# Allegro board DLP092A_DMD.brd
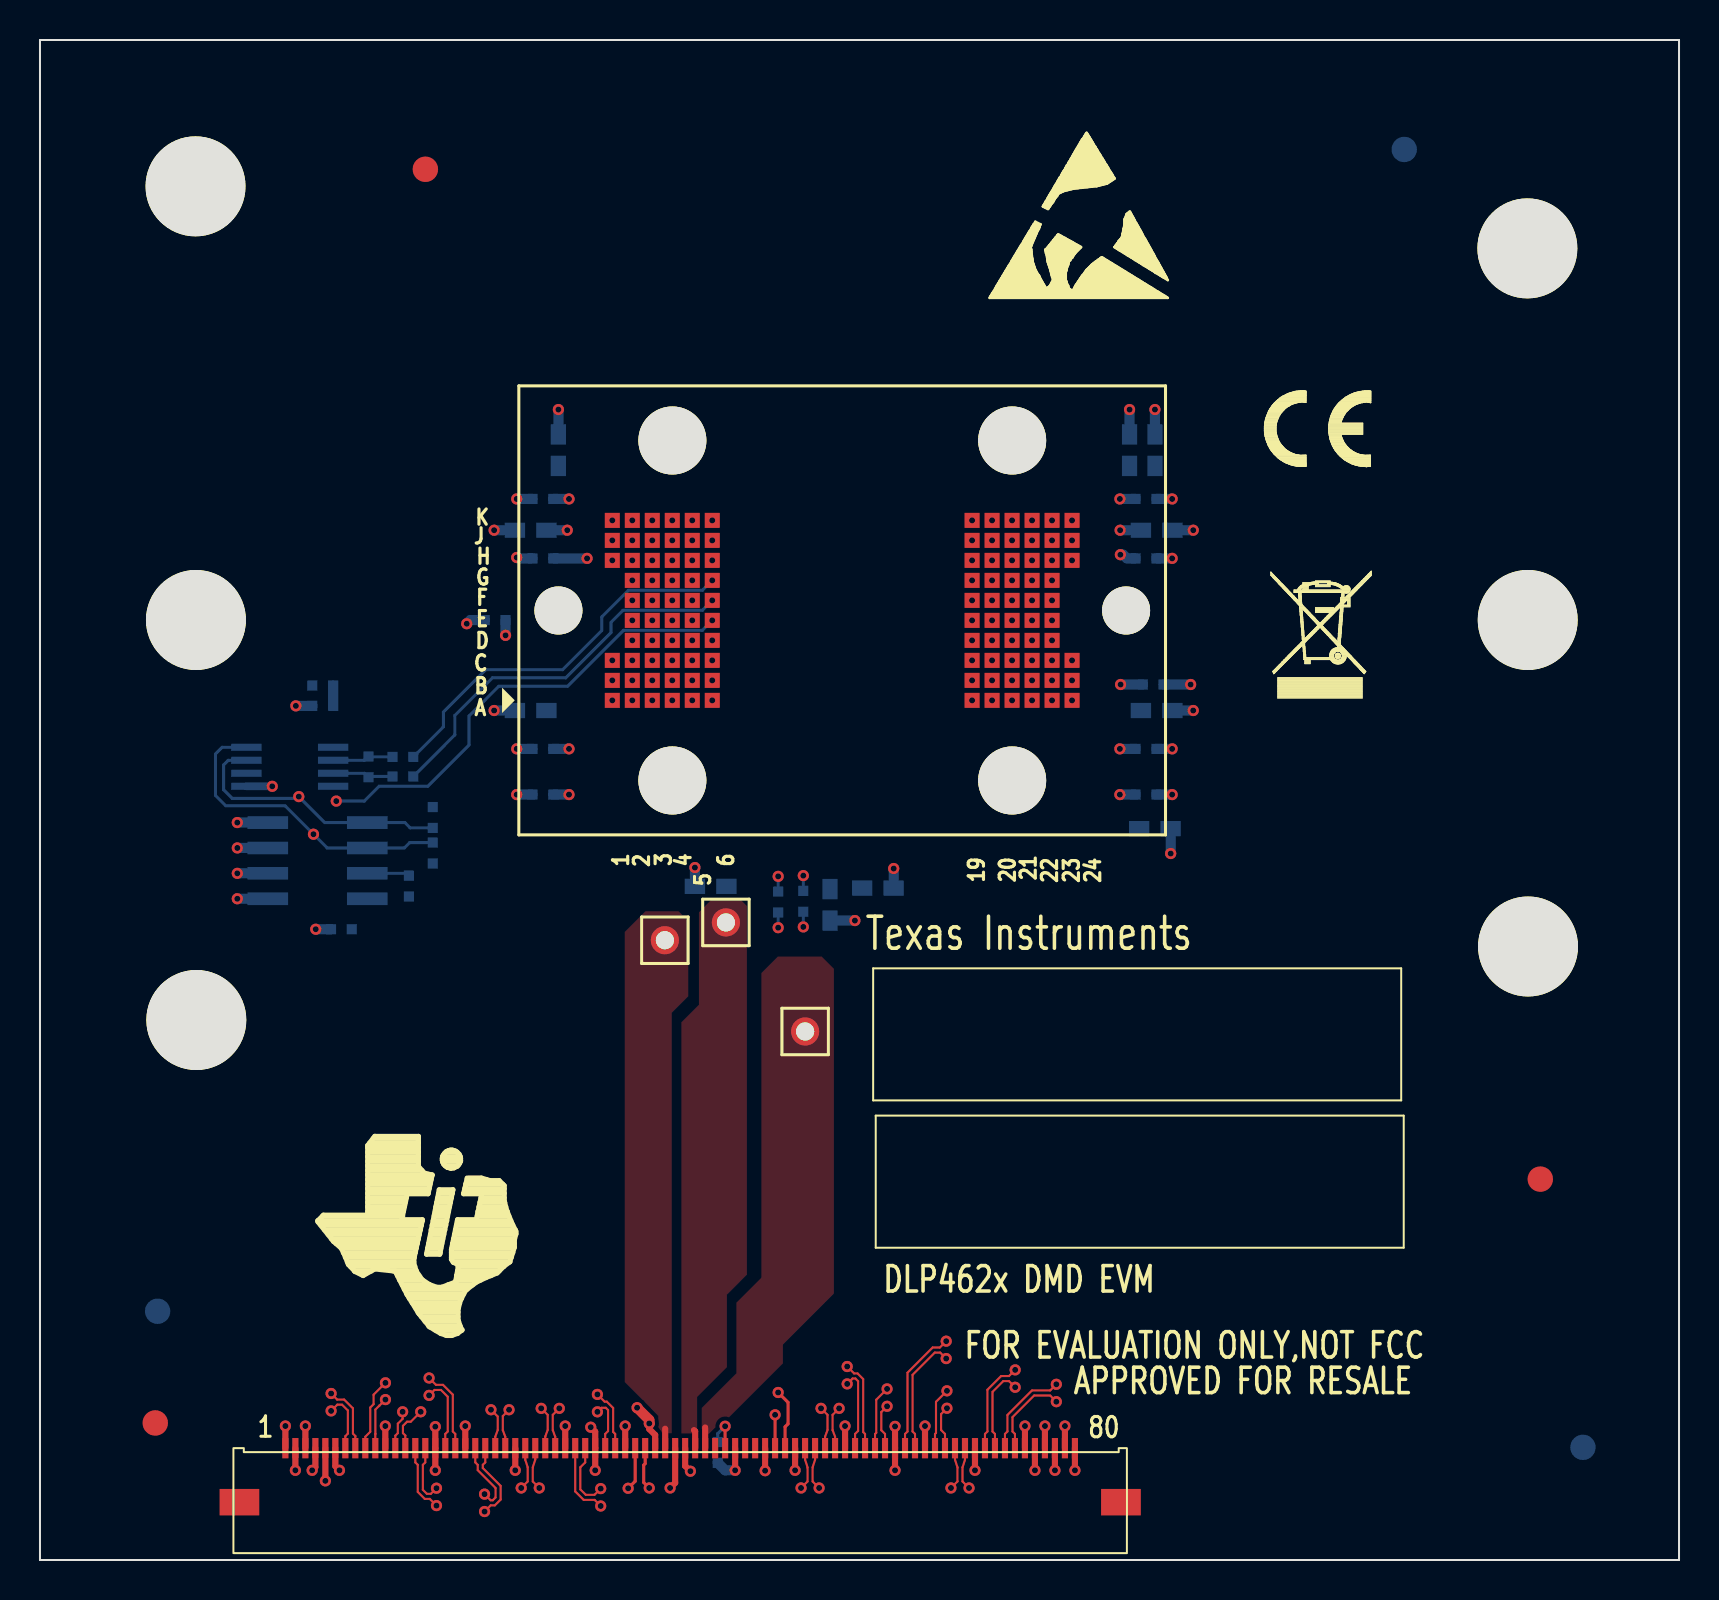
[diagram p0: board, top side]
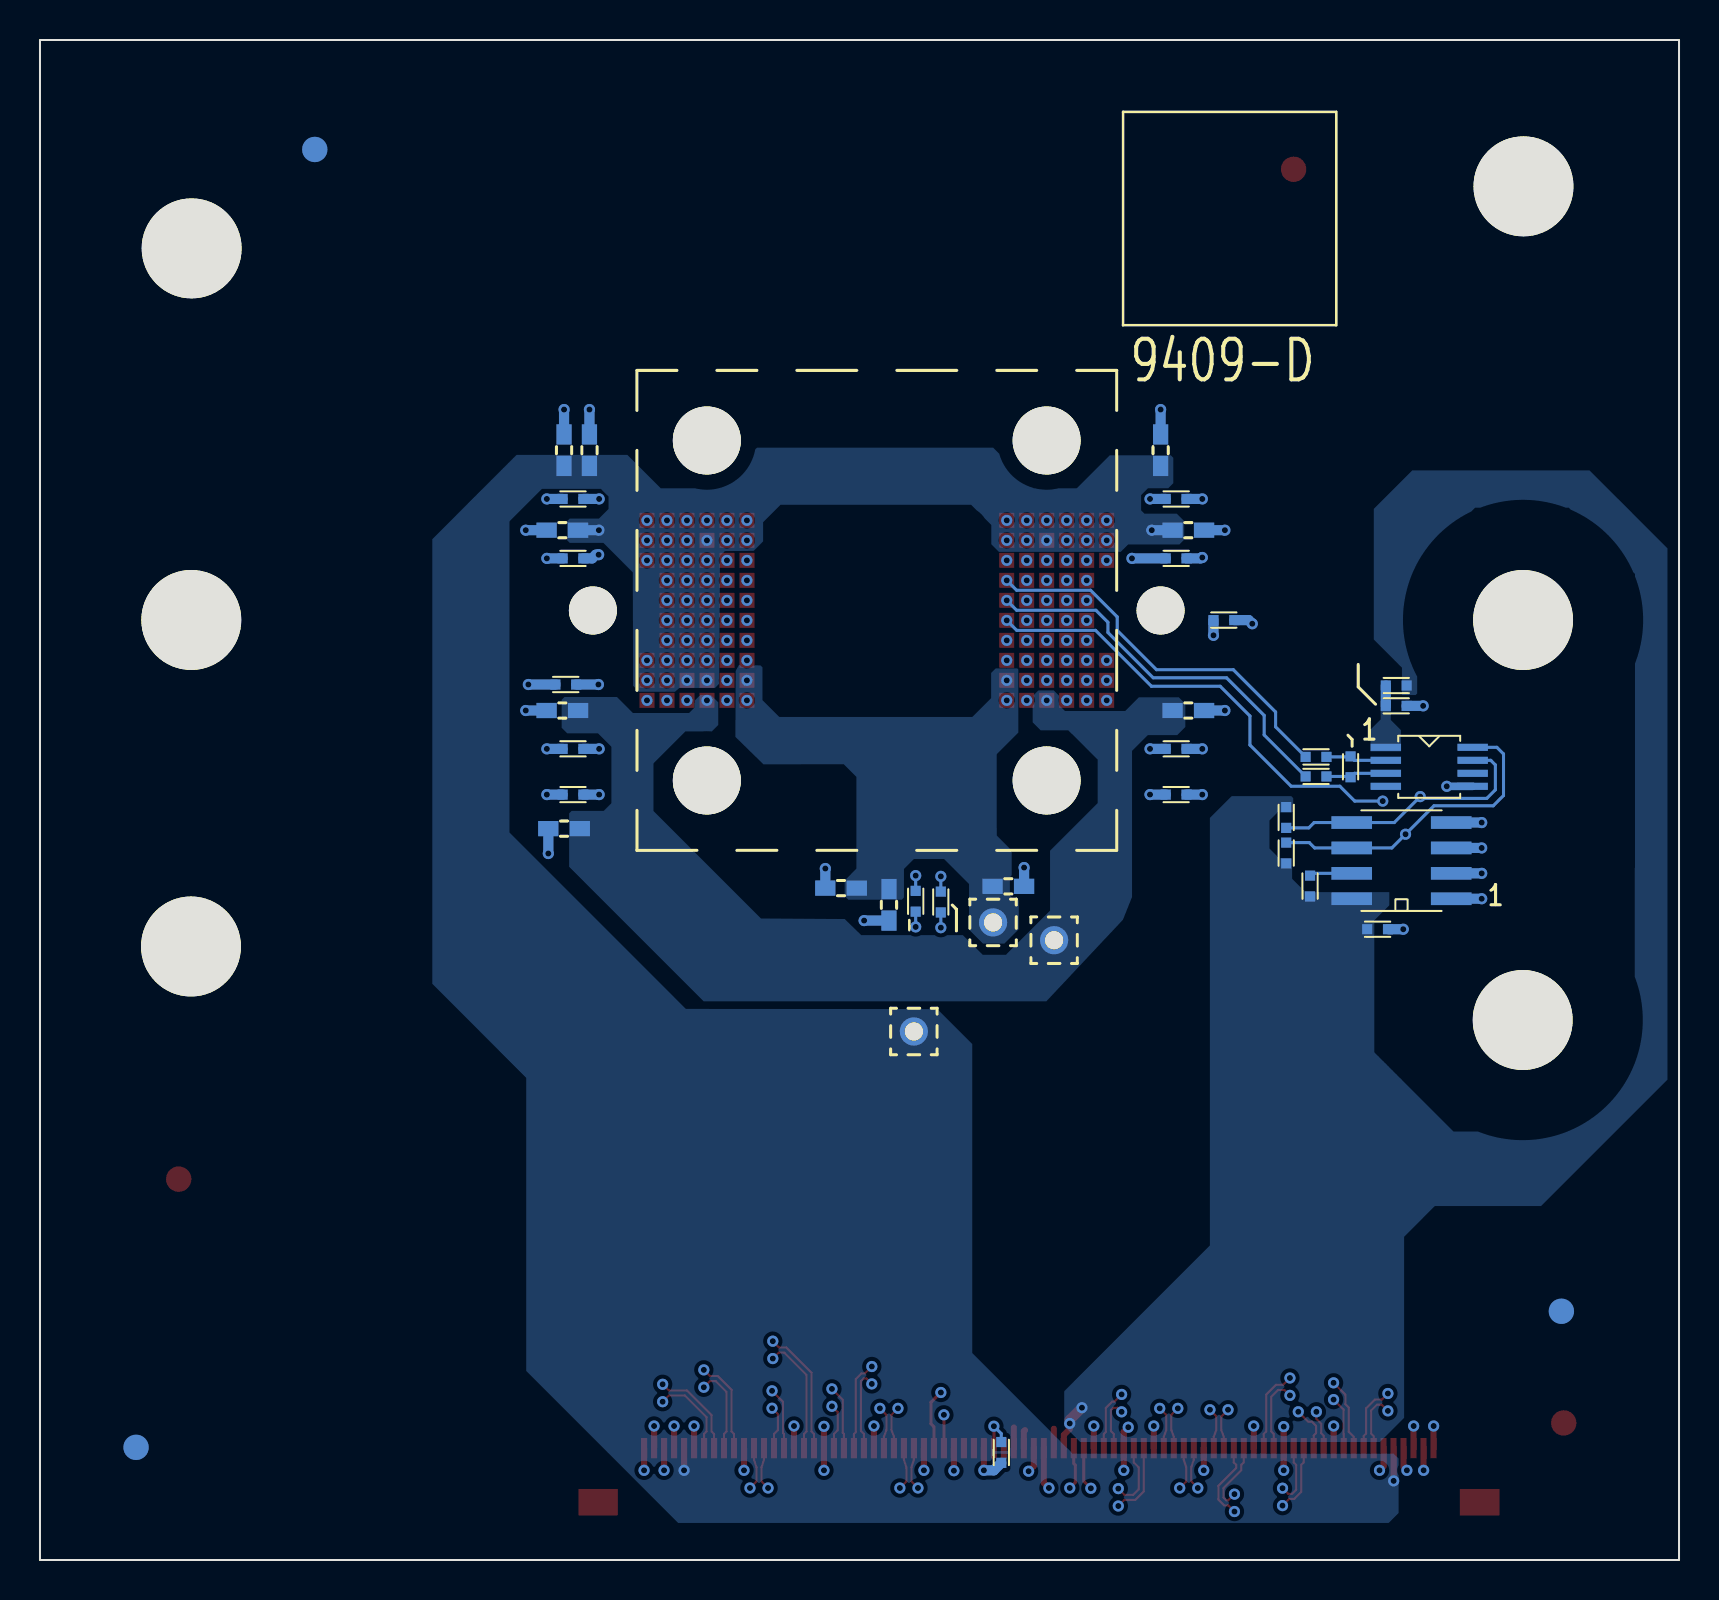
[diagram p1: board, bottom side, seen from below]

Outline 82 x 76 mm; copper layers: TOP, 02GND, 03SIG1, 04SIG2, 05PWR, BOTTOM. Coordinates in mm from the lower left corner of the outline.

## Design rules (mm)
constraint set DEFAULT: min track width 0.152
net group HS_A_CLK: nets HS_A_CLK_N HS_A_CLK_P
net group HS_A_WDATA0: nets HS_A_WDATA0_N HS_A_WDATA0_P
net group HS_A_WDATA1: nets HS_A_WDATA1_N HS_A_WDATA1_P
net group HS_A_WDATA2: nets HS_A_WDATA2_N HS_A_WDATA2_P
net group HS_A_WDATA3: nets HS_A_WDATA3_N HS_A_WDATA3_P
net group HS_A_WDATA4: nets HS_A_WDATA4_N HS_A_WDATA4_P
net group HS_A_WDATA5: nets HS_A_WDATA5_N HS_A_WDATA5_P
net group HS_A_WDATA6: nets HS_A_WDATA6_N HS_A_WDATA6_P
net group HS_A_WDATA7: nets HS_A_WDATA7_N HS_A_WDATA7_P
net group HS_B_CLK: nets HS_B_CLK_N HS_B_CLK_P
net group HS_B_WDATA0: nets HS_B_WDATA0_N HS_B_WDATA0_P
net group HS_B_WDATA1: nets HS_B_WDATA1_N HS_B_WDATA1_P
net group HS_B_WDATA2: nets HS_B_WDATA2_N HS_B_WDATA2_P
net group HS_B_WDATA3: nets HS_B_WDATA3_N HS_B_WDATA3_P
net group HS_B_WDATA4: nets HS_B_WDATA4_N HS_B_WDATA4_P
net group HS_B_WDATA5: nets HS_B_WDATA5_N HS_B_WDATA5_P
net group HS_B_WDATA6: nets HS_B_WDATA6_N HS_B_WDATA6_P
net group HS_B_WDATA7: nets HS_B_WDATA7_N HS_B_WDATA7_P
net group LS_CLK: nets LS_CLK_N LS_CLK_P
net group LS_WDATA: nets LS_WDATA_N LS_WDATA_P

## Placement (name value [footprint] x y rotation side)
C500  0.1uF  [0402]  25.16 53.06 180 bottom
C501  0.1uF  [0402]  25.16 40.56 180 bottom
C502  0.1uF  [0402]  55.33 53.06 0 bottom
C503  0.1uF  [0402]  55.33 38.27 0 bottom
C504  0.22uF  [0603]  24.55 42.48 180 bottom
C505  0.22uF  [0603]  41.92 33.6 0 bottom
C506  0.22uF  [0603]  24.55 51.49 180 bottom
C507  0.1uF  [0402]  25.16 38.27 180 bottom
C510  0.1uF  [0402]  22.77 47 180 bottom
C511  0.22uF  [0603]  55.87 51.49 0 bottom
C512  0.22uF  [0603]  33.55 33.68 180 bottom
C513  0.22uF  [0603]  55.87 42.48 0 bottom
C514  0.1uF  [0402]  15.08 31.54 180 bottom
C515  0.1uF  [0402]  55.69 43.78 0 bottom
C516  0.1uF  [0402]  55.33 40.56 0 bottom
C517  0.1uF  [0402]  25.16 50.08 180 bottom
C518  0.1uF  [0402]  55.33 50.08 0 bottom
C519  100pF  [0402]  16.43 39.66 270 bottom
C520  0.1uF  [0402]  14.15 42.71 180 bottom
C527  4.7uF  [0603]  25.94 55.49 90 bottom
C528  4.7uF  [0603]  55.78 55.49 90 bottom
C529  4.7uF  [0603]  54.51 55.49 90 bottom
C530  4.7uF  [0603]  39.52 32.76 270 bottom
C531  4.7uF  [0603]  55.78 36.57 0 bottom
J1  5051108091  [CONN80-ZIF-FFC-505110_MLX]  32.03 5.59 0 top
NOREF  -  []  -31.09 76.19 180 top
NOREF#2  -  [unnamed#2]  75.06 19.04 0 top
NOREF#3  -  []  74.43 47 90 top
NOREF#4  -  [unnamed#2]  5.77 6.85 0 top
NOREF#5  -  [unnamed#3]  40.11 47.48 0 top
NOREF#6  -  []  0 0 0 top
NOREF#7  -  []  -42.29 -51.11 0 top
NOREF#8  -  []  7.78 68.69 0 top
NOREF#9  -  [unnamed#2]  19.28 69.54 0 top
NOREF#10  -  []  -30.5 -17.2 180 top
NOREF#11  -  []  28.63 42.98 0 top
NOREF#12  -  []  82 76 0 top
NOREF#13  -  []  115.47 -11.56 0 top
NOREF#14  -  []  0 0 0 top
NOREF#15  -  []  74.45 30.68 90 top
NOREF#16  -  []  82 76 0 top
NOREF#17  -  []  7.82 27 90 top
NOREF#18  -  []  100.1 -17.05 180 top
NOREF#19  -  []  51.63 42.98 90 top
NOREF#20  -  []  48.64 38.98 90 top
NOREF#21  -  []  28.63 42.98 0 top
NOREF#22  -  []  23.96 36.26 90 top
NOREF#23  -  []  7.82 27 90 top
NOREF#24  -  []  28.13 59.48 0 top
NOREF#25  -  []  7.8 47 90 top
NOREF#26  -  []  23.96 58.71 0 top
NOREF#27  -  []  74.45 30.68 90 top
NOREF#28  -  []  28.63 42.98 90 top
NOREF#29  -  []  82 0 0 top
NOREF#30  -  [unnamed#2]  5.89 12.44 180 bottom
NOREF#31  -  [unnamed#2]  68.25 70.53 180 bottom
NOREF#32  -  [unnamed#2]  77.19 5.63 180 bottom
NOREF#33  -  []  22.53 67.13 180 bottom
R501  10K  [0402]  19.65 37.13 270 bottom
R502  2.2K  [0402]  33.91 5.38 270 bottom
R503  10K  [0402]  19.65 35.35 90 bottom
R504  10K  [0402]  18.46 33.7 90 bottom
R505  10  [0402]  38.19 32.94 90 bottom
R506  10  [0402]  36.93 32.9 90 bottom
R507  56  [0402]  18.16 40.16 180 bottom
R508  56  [0402]  18.16 39.18 180 bottom
R509  10  [0402]  14.15 43.73 0 bottom
TP505  TP, 36mil Dia  [TP141H91]  38.28 26.43 0 top
TP506  TP, 36mil Dia  [TP141H91]  31.26 30.99 0 top
TP507  TP, 36mil Dia  [TP141H91]  34.32 31.88 0 top
U1  DLP462x  [SKT_2518197]  40.13 47.48 0 top
U500  M24512-DRMN8TP/K  [SOIC8]  13.89 34.97 90 bottom
U501  TMP411A  [SOIC8-DGK_TI]  12.5 39.66 270 bottom

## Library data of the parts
C500-C507 C510-C520 C527-C531 = CAP_NP_dsize
J1 = EM,HDR,80P,1R,2x
R501-R509 = RESISTOR_dsize
TP505-TP507 = EM,TERM,TESTPOINT
U1 = DLP462x
U500 = M24C64
U501 = TMP411

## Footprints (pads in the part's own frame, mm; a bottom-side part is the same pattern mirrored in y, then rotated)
0402
  rect 0.508x0.508 smd: 1(-0.521,0) 2(0.521,0)
0603
  rect 1.016x0.762 smd: 1(-0.787,0) 2(0.787,0)
CONN80-ZIF-FFC-505110_MLX
  rect 1.981x1.321 smd: (-22.05,-2.7) (22.05,-2.7)
  rect 0.305x1.016 smd: 1(-19.75,0) 2(-19.25,0) 3(-18.75,0) 4(-18.25,0) 5(-17.75,0) 6(-17.25,0) 7(-16.75,0) 8(-16.25,0) 9(-15.75,0) 10(-15.25,0) 11(-14.75,0) 12(-14.25,0) 13(-13.75,0) 14(-13.25,0) 15(-12.75,0) 16(-12.25,0) 17(-11.75,0) 18(-11.25,0) 19(-10.75,0) 20(-10.25,0) 21(-9.75,0) 22(-9.25,0) 23(-8.75,0) 24(-8.25,0) 25(-7.75,0) 26(-7.25,0) 27(-6.75,0) 28(-6.25,0) 29(-5.75,0) 30(-5.25,0) 31(-4.75,0) 32(-4.25,0) 33(-3.75,0) 34(-3.25,0) 35(-2.75,0) 36(-2.25,0) 37(-1.75,0) 38(-1.25,0) 39(-0.75,0) 40(-0.25,0) 41(0.25,0) 42(0.75,0) 43(1.25,0) 44(1.75,0) 45(2.25,0) 46(2.75,0) 47(3.25,0) 48(3.75,0) 49(4.25,0) 50(4.75,0) 51(5.25,0) 52(5.75,0) 53(6.25,0) 54(6.75,0) 55(7.25,0) 56(7.75,0) 57(8.25,0) 58(8.75,0) 59(9.25,0) 60(9.75,0) 61(10.25,0) 62(10.75,0) 63(11.25,0) 64(11.75,0) 65(12.25,0) 66(12.75,0) 67(13.25,0) 68(13.75,0) 69(14.25,0) 70(14.75,0) 71(15.25,0) 72(15.75,0) 73(16.25,0) 74(16.75,0) 75(17.25,0) 76(17.75,0) 77(18.25,0) 78(18.75,0) 79(19.25,0) 80(19.75,0)
SKT_2518197
  round 2.4 hole 2.4 unplated: (-14.195,-0.005) (14.205,-0.005)
  round 3.4 hole 3.4 unplated: (-8.495,8.495) (-8.495,-8.505) (8.505,8.495) (8.505,-8.505)
  rect 0.75x0.75 smd: A1(-11.5,-4.5) A2(-10.5,-4.5) A3(-9.5,-4.5) A4(-8.5,-4.5) A5(-7.5,-4.5) A6(-6.5,-4.5) A19(6.5,-4.5) A20(7.5,-4.5) A21(8.5,-4.5) A22(9.5,-4.5) A23(10.5,-4.5) A24(11.5,-4.5) B1(-11.5,-3.5) B2(-10.5,-3.5) B3(-9.5,-3.5) B4(-8.5,-3.5) B5(-7.5,-3.5) B6(-6.5,-3.5) B19(6.5,-3.5) B20(7.5,-3.5) B21(8.5,-3.5) B22(9.5,-3.5) B23(10.5,-3.5) B24(11.5,-3.5) C1(-11.5,-2.5) C2(-10.5,-2.5) C3(-9.5,-2.5) C4(-8.5,-2.5) C5(-7.5,-2.5) C6(-6.5,-2.5) C19(6.5,-2.5) C20(7.5,-2.5) C21(8.5,-2.5) C22(9.5,-2.5) C23(10.5,-2.5) C24(11.5,-2.5) D2(-10.5,-1.5) D3(-9.5,-1.5) D4(-8.5,-1.5) D5(-7.5,-1.5) D6(-6.5,-1.5) D19(6.5,-1.5) D20(7.5,-1.5) D21(8.5,-1.5) D22(9.5,-1.5) D23(10.5,-1.5) E2(-10.5,-0.5) E3(-9.5,-0.5) E4(-8.5,-0.5) E5(-7.5,-0.5) E6(-6.5,-0.5) E19(6.5,-0.5) E20(7.5,-0.5) E21(8.5,-0.5) E22(9.5,-0.5) E23(10.5,-0.5) F2(-10.5,0.5) F3(-9.5,0.5) F4(-8.5,0.5) F5(-7.5,0.5) F6(-6.5,0.5) F19(6.5,0.5) F20(7.5,0.5) F21(8.5,0.5) F22(9.5,0.5) F23(10.5,0.5) G2(-10.5,1.5) G3(-9.5,1.5) G4(-8.5,1.5) G5(-7.5,1.5) G6(-6.5,1.5) G19(6.5,1.5) G20(7.5,1.5) G21(8.5,1.5) G22(9.5,1.5) G23(10.5,1.5) H1(-11.5,2.5) H2(-10.5,2.5) H3(-9.5,2.5) H4(-8.5,2.5) H5(-7.5,2.5) H6(-6.5,2.5) H19(6.5,2.5) H20(7.5,2.5) H21(8.5,2.5) H22(9.5,2.5) H23(10.5,2.5) H24(11.5,2.5) J1(-11.5,3.5) J2(-10.5,3.5) J3(-9.5,3.5) J4(-8.5,3.5) J5(-7.5,3.5) J6(-6.5,3.5) J19(6.5,3.5) J20(7.5,3.5) J21(8.5,3.5) J22(9.5,3.5) J23(10.5,3.5) J24(11.5,3.5) K1(-11.5,4.5) K2(-10.5,4.5) K3(-9.5,4.5) K4(-8.5,4.5) K5(-7.5,4.5) K6(-6.5,4.5) K19(6.5,4.5) K20(7.5,4.5) K21(8.5,4.5) K22(9.5,4.5) K23(10.5,4.5) K24(11.5,4.5)
SOIC8
  rect 0.635x2.032 smd: 1(-1.905,-2.489) 2(-0.635,-2.489) 3(0.635,-2.489) 4(1.905,-2.489) 5(1.905,2.489) 6(0.635,2.489) 7(-0.635,2.489) 8(-1.905,2.489)
SOIC8-DGK_TI
  rect 0.356x1.524 smd: 1(-0.975,-2.173) 2(-0.325,-2.173) 3(0.325,-2.173) 4(0.975,-2.173) 5(0.975,2.173) 6(0.325,2.173) 7(-0.325,2.173) 8(-0.975,2.173)
TP141H91
  round 1.41 hole 0.91: 1(0,0)
unnamed#2
  round 1.27 smd: 1(0,0)
unnamed#3
  round 11 hole 5 unplated: (-32.327,21.203) (-32.288,-20.482) (34.303,18.101) (34.336,-16.806)
  round 8 hole 5 unplated: (-32.307,-0.48) (34.321,-0.479)

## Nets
GND: C500.2 C501.2 C502.2 C503.2 C504.2 C505.2 C506.2 C507.2 C510.2 C511.2 C512.2 C513.2 C514.2 C515.2 C516.2 C517.2 C518.2 C520.2 C527.2 C528.2 C529.2 C530.2 C531.2 J1.3 J1.4 J1.6 J1.11 J1.16 J1.19 J1.24 J1.29 J1.32 J1.35 J1.40 J1.41 J1.46 J1.49 J1.52 J1.57 J1.62 J1.65 J1.70 J1.75 J1.77 J1.78 R502.2 U1.A1 U1.A6 U1.A19 U1.A24 U1.B2 U1.B5 U1.B20 U1.B23 U1.C19 U1.C21 U1.C22 U1.D3 U1.D5 U1.D6 U1.D20 U1.D22 U1.E4 U1.E21 U1.F3 U1.F21 U1.F22 U1.G4 U1.G19 U1.G22 U1.H3 U1.H4 U1.H6 U1.H19 U1.H21 U1.J2 U1.J5(VSS#J5) U1.J20 U1.J22 U1.J23 U500.1 U500.2 U500.3 U500.4 U501.5
DEN_ARSTZ: J1.45 R502.1 U1.E6
EEPROM_WCZ: R504.2 U500.7(WCZ)
HS_A_CLK_N: J1.18 U1.J1
HS_A_CLK_P: J1.17 U1.H1
HS_A_WDATA0_N: J1.28 U1.A3
HS_A_WDATA0_P: J1.27 U1.A2
HS_A_WDATA1_N: J1.26 U1.B1
HS_A_WDATA1_P: J1.25 U1.C1
HS_A_WDATA2_N: J1.23 U1.C2
HS_A_WDATA2_P: J1.22 U1.D2
HS_A_WDATA3_N: J1.21 U1.F2
HS_A_WDATA3_P: J1.20 U1.E2
HS_A_WDATA4_N: J1.15 U1.H2
HS_A_WDATA4_P: J1.14 U1.G2
HS_A_WDATA5_N: J1.13 U1.K1
HS_A_WDATA5_P: J1.12 U1.K2
HS_A_WDATA6_N: J1.10 U1.K4
HS_A_WDATA6_P: J1.9 U1.K3
HS_A_WDATA7_N: J1.8 U1.K6
HS_A_WDATA7_P: J1.7 U1.K5
HS_B_CLK_N: J1.63 U1.J24
HS_B_CLK_P: J1.64 U1.H24
HS_B_WDATA0_N: J1.53 U1.A22
HS_B_WDATA0_P: J1.54 U1.A23
HS_B_WDATA1_N: J1.55 U1.B24
HS_B_WDATA1_P: J1.56 U1.C24
HS_B_WDATA2_N: J1.58 U1.D23
HS_B_WDATA2_P: J1.59 U1.C23
HS_B_WDATA3_N: J1.60 U1.F23
HS_B_WDATA3_P: J1.61 U1.E23
HS_B_WDATA4_N: J1.66 U1.H23
HS_B_WDATA4_P: J1.67 U1.G23
HS_B_WDATA5_N: J1.68 U1.K24
HS_B_WDATA5_P: J1.69 U1.K23
HS_B_WDATA6_N: J1.71 U1.K21
HS_B_WDATA6_P: J1.72 U1.K22
HS_B_WDATA7_N: J1.73 U1.K19
HS_B_WDATA7_P: J1.74 U1.K20
LS_CLK_N: J1.34 U1.C3
LS_CLK_P: J1.33 U1.C4
LS_RDATA_A: J1.36 R506.1
LS_RDATA_A_S: R506.2 U1.E19
LS_RDATA_B: J1.37 R505.1
LS_RDATA_B_S: R505.2 U1.F19
LS_WDATA_N: J1.31 U1.C5
LS_WDATA_P: J1.30 U1.C6
MSTR_SCL: J1.50 R503.2 U500.6 U501.8
MSTR_SDA: J1.51 R501.2 U500.5 U501.7
P1P8V: C500.1 C501.1 C502.1 C503.1 C507.1 C510.1 C515.1 C516.1 C517.1 C518.1 J1.1 J1.2 J1.79 J1.80 U1.A5 U1.A20 U1.C20 U1.D4 U1.D19 U1.D21 U1.E3 U1.E5 U1.E20 U1.E22 U1.F4 U1.F5 U1.F20 U1.G3 U1.G5 U1.G20 U1.G21 U1.H5 U1.H20 U1.H22 U1.J3 U1.J6 U1.J19
P3P3V: C514.1 J1.38 R501.1 R503.1 R504.1 R509.1 U500.8
P3P3V_TMP: C520.1 R509.2 U501.1
TEMP1N: R508.1 U1.F6
TEMP1N_S: C519.2 R508.2 U501.3
TEMP1P: R507.1 U1.G6
TEMP1P_S: C519.1 R507.2 U501.2
V_BIAS: C504.1 C513.1 C531.1 J1.39 TP506.1(P1) U1.A4 U1.A21
V_OFFSET: C506.1 C511.1 C527.1 C528.1 C529.1 J1.5 J1.43 J1.76 TP505.1(P1) U1.B3 U1.B4 U1.B21 U1.B22 U1.J4 U1.J21
V_RESET: C505.1 C512.1 C530.1 J1.42 TP507.1(P1) U1.B6 U1.B19

Pads without a net: J1 44 47 48; NOREF#2 1; NOREF#4 1; NOREF#9 1; NOREF#30 1; NOREF#31 1; NOREF#32 1; U501 4 6

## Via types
v1: diameter 0.559, hole 0.305, TOP to BOTTOM, 237 vias

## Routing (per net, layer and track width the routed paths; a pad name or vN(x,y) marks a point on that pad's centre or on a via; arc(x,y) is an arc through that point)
GND: length 60
  TOP w0.305: J1.75 v1(49.28,6.7) ; J1.29 v1(26.28,6.7) ; v1(31.52,3.6) 31.78,3.86 J1.40 ; v1(42.78,4.48) J1.62 v1(42.78,6.68) ; J1.24 v1(23.78,4.48) ; J1.19 v1(21.28,6.7) ; v1(19.78,6.67) J1.16 v1(19.78,4.48) ; v1(32.54,4.44) 32.28,4.7 J1.41 ; J1.6 14.78,4.7 14.98,4.49 v1(14.98,4.48) ; v1(13.62,4.48) 13.78,4.65 J1.4 ; J1.35 v1(29.28,6.7) ; J1.49 v1(36.28,4.46) ; J1.52 v1(37.78,4.48) ; J1.78 v1(50.78,4.48) ; J1.57 v1(40.28,6.7) ; v1(27.78,4.48) J1.32 27.78,6.42 v1(27.55,6.64) ; J1.3 v1(13.28,6.7) ; J1.70 v1(46.78,4.48) ; J1.11 v1(17.28,6.7) ; J1.46 v1(34.78,4.48) ; J1.77 v1(50.28,6.7) ; J1.65 v1(44.28,6.7)
  BOTTOM w0.381: U501.5 v1(11.62,38.69)
  BOTTOM w0.508: C528.2 v1(55.78,57.53) ; v1(23.85,50.13) 23.89,50.13 23.93,50.08 C517.2 ; C530.2 v1(40.77,31.97) ; R502.2 34.28,4.48 v1(34.78,4.48) ; C529.2 v1(54.51,57.53) ; U500.4 v1(9.87,36.87) ; C500.2 v1(23.85,53.06) ; C512.2 v1(32.77,34.62) ; U500.3 v1(9.87,35.6) ; C502.2 v1(56.64,53.06) ; U500.1 v1(9.87,33.06) ; C515.2 v1(57.57,43.78) ; C510.2 21.53,47 v1(21.35,46.82) ; C503.2 v1(56.64,38.27) ; C520.2 v1(12.8,42.71) ; C518.2 v1(56.64,50.08) ; C501.2 v1(23.85,40.56) ; C507.2 v1(23.85,38.27) ; C511.2 v1(57.7,51.49) ; C513.2 v1(57.7,42.48) ; C527.2 v1(25.94,57.53) ; C516.2 v1(56.64,40.56) ; U500.2 v1(9.87,34.33) ; C505.2 v1(42.71,34.58) ; C531.2 v1(56.57,35.33) ; C504.2 v1(22.72,42.48) ; C514.2 v1(13.8,31.54) ; C506.2 v1(22.72,51.49)
  vias: v1(28.63,42.98) v1(29.63,50.98) v1(29.63,43.98) v1(30.63,49.98) v1(30.63,47.98) v1(30.63,45.98) v1(31.63,49.98) v1(31.63,48.98) v1(31.63,46.98) v1(32.63,50.98) v1(32.63,45.98) v1(32.63,43.98) v1(33.63,49.98) v1(33.63,45.98) v1(33.63,42.98) v1(46.63,49.98) v1(46.63,48.98) v1(46.63,44.98) v1(46.63,42.98) v1(47.63,50.98) v1(47.63,45.98) v1(47.63,43.98) v1(48.63,49.98) v1(48.63,47.98) v1(48.63,46.98) v1(48.63,44.98) v1(49.63,50.98) v1(49.63,48.98) v1(49.63,47.98) v1(49.63,45.98) v1(49.63,44.98) v1(50.63,50.98) v1(50.63,43.98) v1(51.63,42.98)
DEN_ARSTZ: length 87.5
  TOP w0.152: J1.45 v1(34.28,6.69)
  04SIG2 w0.14: v1(14.82,37.95) 14.82,30.78 13.38,29.34 13.38,23.39 11.17,21.18 11.17,5.13 14.53,1.78 31.43,1.78 33.54,3.89 33.54,5.95 v1(34.28,6.69)
  BOTTOM w0.152: R502.1 33.91,6.32 v1(34.28,6.69) ; v1(33.63,46.98) 33.13,46.48 29.19,46.48 26.39,43.69 22.95,43.69 21.46,42.2 21.46,40.75 19.41,38.69 16.97,38.69 16.22,37.95 v1(14.82,37.95)
EEPROM_WCZ: length 2.1
  BOTTOM w0.152: R504.2 18.34,34.33 U500.7
HS_A_CLK_N: length 53.4
  TOP w0.104: J1.18 20.78,6.3 20.65,6.43 20.65,8.27 20.17,8.76 19.81,8.76 v1(19.47,9.1)
  03SIG1 w0.102: v1(19.47,9.1) 19.68,9.32 19.68,47.56 23.05,50.92 27.62,50.92 27.88,50.66 28.31,50.66 v1(28.63,50.98)
HS_A_CLK_P: length 53.5
  TOP w0.104: v1(19.47,8.23) 19.74,8.5 20.06,8.5 20.4,8.16 20.4,6.43 20.28,6.3 J1.17
  03SIG1 w0.102: v1(28.63,49.98) 28.21,50.41 27.77,50.41 27.52,50.67 23.15,50.67 19.94,47.45 19.94,8.7 v1(19.47,8.23)
HS_A_WDATA0_N: length 42.2
  TOP w0.104: v1(25.98,7.58) 25.65,7.26 25.65,6.49 25.78,6.16 J1.28
  03SIG1 w0.102: v1(30.63,42.98) 30.24,42.59 30.24,42.23 27.78,39.77 26.52,39.77 25.87,39.11 25.87,36.37 26.88,35.36 26.88,32.65 26.24,32 26.24,15.42 24.62,13.81 24.62,10.81 25.65,9.77 25.65,7.91 v1(25.98,7.58)
HS_A_WDATA0_P: length 42.2
  TOP w0.104: v1(25.07,7.58) 25.4,7.26 25.4,6.5 25.28,6.17 J1.27
  03SIG1 w0.102: v1(25.07,7.58) 25.4,7.91 25.4,9.67 24.37,10.7 24.37,13.92 25.98,15.53 25.98,32.11 26.63,32.75 26.63,35.25 25.61,36.27 25.61,39.22 26.42,40.02 27.67,40.02 29.99,42.34 29.99,42.63 v1(29.63,42.98)
HS_A_WDATA1_N: length 46.3
  TOP w0.104: v1(24.98,3.6) 24.65,3.93 24.65,4.64 24.78,5.01 J1.26
  03SIG1 w0.102: v1(28.63,43.98) 28.31,44.31 28.16,44.31 27.5,43.64 27.5,42.42 24.7,39.62 24.7,15.45 23.59,14.34 23.59,10.25 24.31,9.54 24.31,7.41 24.65,7.06 24.65,6.44 24.9,6.19 24.9,5.89 24.65,5.64 24.65,5.33 24.9,5.08 24.9,4.78 24.65,4.53 24.65,3.93 v1(24.98,3.6)
HS_A_WDATA1_P: length 46.4
  TOP w0.104: v1(24.07,3.6) 24.4,3.93 24.4,4.64 24.28,5.02 J1.25
  03SIG1 w0.102: v1(24.07,3.6) 24.4,3.93 24.4,6.96 24.05,7.31 24.05,9.43 23.34,10.14 23.34,14.45 24.45,15.55 24.45,39.73 27.24,42.52 27.24,43.75 28.06,44.56 28.21,44.56 v1(28.63,44.98)
HS_A_WDATA2_N: length 45
  TOP w0.104: v1(23.47,7.51) 23.15,7.2 23.15,6.49 23.28,6.16 J1.23
  03SIG1 w0.102: v1(23.47,7.51) 23.14,7.84 23.14,8.67 22.72,9.09 22.72,9.87 22.71,9.88 22.71,19.7 23.2,20.19 23.2,41.05 24.37,42.21 24.37,42.79 25.58,44 26.92,44 28.52,45.6 28.79,45.6 29.02,45.37 29.25,45.37 v1(29.63,44.98)
HS_A_WDATA2_P: length 45.5
  TOP w0.104: J1.22 22.78,6.17 22.9,6.5 22.9,7.17 v1(22.56,7.51)
  03SIG1 w0.102: v1(22.56,7.51) 22.89,7.84 22.89,8.56 22.46,8.99 22.46,9.76 22.45,9.77 22.45,19.8 22.95,20.3 22.95,41.15 24.12,42.32 24.12,42.9 25.48,44.25 26.82,44.25 28.41,45.85 28.89,45.85 29.13,45.62 29.27,45.62 v1(29.63,45.98)
HS_A_WDATA3_N: length 55.8
  TOP w0.104: J1.21 22.28,4.88 22.15,4.76 22.15,4.6 23.05,3.71 23.05,3.02 22.76,2.73 22.55,2.73 v1(22.24,2.42)
  03SIG1 w0.102: v1(22.24,2.42) 21.93,2.73 21.68,2.73 21.42,2.99 21.42,4.11 21.88,4.57 21.88,7.06 21.5,7.44 21.5,20.45 21.96,20.9 21.96,42.83 24.41,45.28 27.01,45.28 28.23,46.5 28.23,47.34 28.62,47.72 29.37,47.72 v1(29.63,47.98)
HS_A_WDATA3_P: length 55.2
  TOP w0.104: v1(22.24,3.29) 22.55,2.99 22.65,2.99 22.79,3.13 22.79,3.6 21.9,4.49 21.9,4.76 21.78,4.88 J1.20
  03SIG1 w0.102: v1(29.63,46.98) 29.63,47.35 29.52,47.47 28.72,47.47 28.49,47.23 28.49,46.4 27.11,45.02 24.51,45.02 22.21,42.72 22.21,20.8 21.75,20.34 21.75,7.54 22.13,7.16 22.13,6.96 22.38,6.72 22.38,6.41 22.13,6.16 22.13,5.86 22.38,5.61 22.38,5.3 22.13,5.06 22.13,4.46 21.68,4.01 21.68,3.1 21.79,2.99 21.93,2.99 v1(22.24,3.29)
HS_A_WDATA4_N: length 57.6
  TOP w0.104: J1.15 19.28,4.88 19.15,4.76 19.15,3.51 19.36,3.31 19.56,3.31 v1(19.84,3.59)
  03SIG1 w0.102: v1(29.63,49.98) 29.26,49.61 29.01,49.61 28.43,49.03 27.62,49.03 26.84,49.8 24.55,49.8 23.3,48.56 23.3,47.62 22.91,47.23 20.57,44.89 20.57,7.95 20.39,7.77 20.39,3.45 20.26,3.31 20.11,3.31 v1(19.84,3.59)
HS_A_WDATA4_P: length 58.1
  TOP w0.104: v1(19.84,2.72) 19.5,3.06 19.25,3.06 18.9,3.41 18.9,4.76 18.78,4.88 J1.14
  03SIG1 w0.102: v1(29.63,48.98) 29.26,49.36 29.12,49.36 28.53,48.77 27.51,48.77 26.74,49.55 24.65,49.55 23.56,48.45 23.56,47.52 23.16,47.13 20.83,44.79 20.83,7.84 20.65,7.66 20.65,3.34 20.36,3.06 20.17,3.06 v1(19.84,2.72)
HS_A_WDATA5_N: length 56.8
  TOP w0.104: v1(19.05,7.41) 18.55,6.92 18.36,6.92 18.16,6.71 18.16,6.34 18.28,6.23 J1.13
  03SIG1 w0.102: v1(28.63,51.98) 29,52.35 29,52.59 28.87,52.72 28.31,52.72 27.78,52.19 22.65,52.19 18.11,47.64 18.11,11.98 18.72,11.37 18.72,7.74 v1(19.05,7.41)
HS_A_WDATA5_P: length 57.2
  TOP w0.104: v1(18.14,7.41) 18.14,7.06 17.9,6.82 17.9,6.34 17.78,6.22 J1.12
  03SIG1 w0.102: v1(29.63,51.98) 29.25,52.37 29.25,52.7 28.97,52.98 28.2,52.98 27.67,52.44 22.55,52.44 17.85,47.75 17.85,11.88 18.46,11.27 18.46,7.73 v1(18.14,7.41)
HS_A_WDATA6_N: length 61.4
  TOP w0.104: J1.10 16.78,6.3 16.78,6.3 16.78,7.52 16.98,7.72 16.98,7.72 v1(17.28,8.02)
  03SIG1 w0.102: v1(17.28,8.02) 16.71,8.59 16.71,9.07 16.38,9.4 16.38,47.54 22.67,53.83 29.09,53.83 30.1,52.82 31.25,52.82 31.5,52.57 31.5,52.12 v1(31.63,51.98)
HS_A_WDATA6_P: length 61.1
  TOP w0.104: v1(17.28,8.86) 16.69,8.27 16.69,7.79 16.52,7.62 16.52,6.41 16.28,6.16 J1.9
  03SIG1 w0.102: v1(30.63,51.98) 30.97,51.98 31.24,52.26 31.24,52.46 31.14,52.56 30,52.56 28.99,53.58 22.78,53.58 16.63,47.43 16.63,9.51 v1(17.28,8.86)
HS_A_WDATA7_N: length 65.5
  TOP w0.104: v1(14.56,8.33) 14.87,8.02 15.22,8.02 15.66,7.58 15.66,6.32 15.78,6.2 J1.8
  03SIG1 w0.102: v1(14.56,8.33) 14.56,27.41 15.45,28.29 15.45,47.64 22.31,54.5 29.19,54.5 30.31,53.38 32.71,53.38 33.26,52.83 33.26,52.36 v1(33.63,51.98)
HS_A_WDATA7_P: length 65.5
  TOP w0.104: J1.7 15.28,6.19 15.4,6.32 15.4,7.48 15.11,7.77 14.88,7.77 v1(14.56,7.46)
  03SIG1 w0.102: v1(32.63,51.98) 33.01,52.36 33.01,52.72 32.6,53.12 30.21,53.12 29.09,54.25 22.42,54.25 15.7,47.53 15.7,28.19 14.82,27.3 14.82,8.88 15.18,8.52 15.18,8.07 v1(14.56,7.46)
HS_B_CLK_N: length 58.1
  TOP w0.104: J1.63 43.28,6.3 43.4,6.43 43.4,9.36 44.66,10.62 45.02,10.62 v1(45.34,10.94)
  03SIG1 w0.102: v1(51.63,50.98) 52.02,50.59 53.1,50.59 53.49,50.99 56.76,50.99 58.5,49.25 58.5,34.56 46.03,22.09 46.03,12.06 45.34,11.37 v1(45.34,10.94)
HS_B_CLK_P: length 58.4
  TOP w0.104: J1.64 43.78,6.3 43.65,6.43 43.65,9.26 44.77,10.37 45.04,10.37 v1(45.34,10.07)
  03SIG1 w0.102: v1(45.34,10.07) 44.8,10.61 44.8,11.19 45.77,12.17 45.77,22.19 58.24,34.66 58.24,49.15 56.65,50.74 53.6,50.74 53.2,50.34 51.99,50.34 v1(51.63,49.98)
HS_B_WDATA0_N: length 48.2
  TOP w0.104: J1.53 38.28,5.02 38.4,4.64 38.4,3.93 v1(38.07,3.6)
  03SIG1 w0.102: v1(49.63,42.98) 50.01,42.61 50.01,42.2 49.69,41.88 47.27,41.88 39.58,34.19 39.58,16.25 38.26,14.94 38.26,6.79 38.4,6.65 38.4,3.93 v1(38.07,3.6)
HS_B_WDATA0_P: length 48.2
  TOP w0.104: J1.54 38.78,5.01 38.65,4.64 38.65,3.93 v1(38.98,3.6)
  03SIG1 w0.102: v1(38.98,3.6) 38.65,3.93 38.65,6.75 38.52,6.89 38.52,14.83 39.83,16.14 39.83,34.08 47.38,41.63 49.8,41.63 50.26,42.1 50.26,42.61 v1(50.63,42.98)
HS_B_WDATA1_N: length 45.7
  TOP w0.104: v1(39.07,7.58) 39.4,7.26 39.4,6.5 39.28,6.17 J1.55
  03SIG1 w0.102: v1(39.07,7.58) 39.4,7.91 39.4,13.18 40.67,14.45 40.67,27.07 52.9,39.31 52.9,43.69 52.23,44.36 52.01,44.36 v1(51.63,43.98)
HS_B_WDATA1_P: length 46.1
  TOP w0.104: J1.56 39.78,6.16 39.65,6.49 39.65,7.26 v1(39.98,7.58)
  03SIG1 w0.102: v1(39.98,7.58) 39.65,7.91 39.65,13.08 40.92,14.35 40.92,26.97 53.15,39.2 53.15,43.79 52.33,44.61 52.01,44.61 v1(51.63,44.98)
HS_B_WDATA2_N: length 50.7
  TOP w0.104: v1(40.38,8.81) 40.62,9.04 40.62,9.04 40.66,9.07 40.8,9.07 40.93,8.94 40.93,6.46 40.78,6.3 J1.58
  03SIG1 w0.102: v1(40.38,8.81) 40.67,9.09 40.96,9.09 41.21,9.35 41.21,12.35 41.94,13.08 41.94,26.9 54.89,39.85 54.89,44.19 54.51,44.57 53.46,44.57 52.31,45.72 50.9,45.72 v1(50.63,45.98)
HS_B_WDATA2_P: length 50.4
  TOP w0.104: v1(40.38,9.68) 40.73,9.33 40.9,9.33 41.18,9.05 41.18,6.4 41.28,6.3 J1.59
  03SIG1 w0.102: v1(40.38,9.68) 40.71,9.35 40.85,9.35 40.96,9.45 40.96,12.45 41.68,13.18 41.68,27 54.64,39.96 54.64,44.09 54.41,44.32 53.36,44.32 52.21,45.47 51.12,45.47 v1(50.63,44.98)
HS_B_WDATA3_N: length 51.6
  TOP w0.104: v1(42.38,8.56) 41.84,8.01 41.84,6.36 41.78,6.3 J1.60
  03SIG1 w0.102: v1(42.38,8.56) 41.89,9.04 41.89,10.81 42.9,11.81 42.9,25.95 55.77,38.81 55.77,44.3 54.83,45.24 53.65,45.24 51.29,47.59 51.03,47.59 v1(50.63,47.98)
HS_B_WDATA3_P: length 51.2
  TOP w0.104: v1(42.38,7.69) 42.09,7.4 42.09,6.49 42.28,6.3 J1.61
  03SIG1 w0.102: v1(50.63,46.98) 50.99,47.34 51.19,47.34 53.54,44.98 54.73,44.98 55.51,44.2 55.51,38.92 42.64,26.05 42.64,11.92 41.64,10.91 41.64,8.94 41.82,8.76 41.82,8.2 42.34,7.69 v1(42.38,7.69)
HS_B_WDATA4_N: length 56.4
  TOP w0.104: J1.66 44.78,6.3 44.83,6.35 44.83,7.91 v1(45.38,8.46)
  03SIG1 w0.102: v1(45.38,8.46) 44.23,9.6 44.23,24.84 57.39,38 57.39,41.65 56.82,42.22 56.82,48.48 55.54,49.76 53.36,49.76 53,49.41 51.49,49.41 51.33,49.57 51.05,49.57 v1(50.63,49.98)
HS_B_WDATA4_P: length 56
  TOP w0.104: J1.67 45.28,6.3 45.08,6.5 45.08,7.3 v1(45.38,7.59)
  03SIG1 w0.102: v1(45.38,7.59) 44.74,8.22 44.74,8.73 43.98,9.5 43.98,24.94 57.14,38.1 57.14,41.54 56.57,42.11 56.57,48.38 55.43,49.51 53.46,49.51 53.11,49.16 51.39,49.16 51.22,49.32 50.97,49.32 v1(50.63,48.98)
HS_B_WDATA5_N: length 65
  TOP w0.104: v1(45.57,3.6) 45.9,3.93 45.9,4.64 45.78,5.02 J1.68
  03SIG1 w0.102: v1(45.57,3.6) 45.89,3.91 45.89,4.75 46.91,5.78 46.91,6.3 46.66,6.55 46.66,6.85 46.91,7.1 46.91,7.41 46.66,7.66 46.66,7.96 46.91,8.21 46.91,21.71 59.31,34.11 59.31,50.84 57.94,52.21 53.68,52.21 53.3,52.59 51.37,52.59 51.27,52.49 51.27,52.35 v1(51.63,51.98)
HS_B_WDATA5_P: length 65.4
  TOP w0.104: v1(46.48,3.6) 46.15,3.93 46.15,4.64 46.28,5.01 J1.69
  03SIG1 w0.102: v1(46.48,3.6) 46.14,3.94 46.14,4.65 47.17,5.67 47.17,21.6 59.56,34 59.56,50.95 58.05,52.47 53.79,52.47 53.4,52.85 51.26,52.85 51.01,52.6 51.01,52.36 v1(50.63,51.98)
HS_B_WDATA6_N: length 65.1
  TOP w0.104: J1.71 47.28,6.3 47.4,6.43 47.4,8.51 48.09,9.2 48.48,9.2 v1(48.79,9.51)
  03SIG1 w0.102: v1(48.63,51.98) 49,52.35 49,52.61 49.25,52.86 50.37,52.86 51.36,53.85 57.67,53.85 60.48,51.04 60.48,33.43 49.54,22.49 49.54,10.76 48.79,10 v1(48.79,9.51)
HS_B_WDATA6_P: length 65
  TOP w0.104: J1.72 47.78,6.3 47.65,6.43 47.65,8.41 48.19,8.94 48.48,8.94 v1(48.79,8.64)
  03SIG1 w0.102: v1(49.63,51.98) 49.63,51.98 49.26,52.35 49.26,52.5 49.36,52.6 50.48,52.6 51.47,53.59 57.56,53.59 60.23,50.93 60.23,33.53 49.29,22.6 49.29,10.86 48.24,9.81 48.24,9.18 v1(48.79,8.64)
HS_B_WDATA7_N: length 68.9
  TOP w0.104: v1(50.85,8.79) 50.54,8.48 49.63,8.48 48.4,7.25 48.4,6.43 48.28,6.3 J1.73
  03SIG1 w0.102: v1(50.85,8.79) 50.85,9.24 51.7,10.09 51.7,22.57 61.38,32.25 61.38,51.14 58.02,54.5 51.04,54.5 49.96,53.42 47.79,53.42 47.01,52.64 47.01,52.36 v1(46.63,51.98)
HS_B_WDATA7_P: length 68.8
  TOP w0.104: J1.74 48.78,6.3 48.65,6.43 48.65,7.14 49.73,8.22 50.54,8.22 v1(50.85,7.92)
  03SIG1 w0.102: v1(50.85,7.92) 50.3,8.46 50.3,9.06 51.44,10.2 51.44,22.67 61.13,32.36 61.13,51.03 57.91,54.25 51.15,54.25 50.07,53.17 47.89,53.17 47.26,52.53 47.26,52.36 v1(47.63,51.98)
LS_CLK_N: length 44.4
  TOP w0.104: J1.34 28.78,6.3 28.67,6.41 28.67,7.6 28.36,7.92 28.25,7.92 v1(27.89,8.28)
  03SIG1 w0.102: v1(30.63,44.98) 31.16,44.45 31.16,42.57 27.83,39.23 27.83,36.63 29.15,35.31 29.15,34.02 27.83,32.7 27.83,16.29 26.72,15.18 26.72,10.74 28.41,9.04 28.41,8.19 28.28,8.05 28.11,8.05 v1(27.89,8.28)
LS_CLK_P: length 45
  TOP w0.104: v1(27.89,7.41) 28.09,7.61 28.31,7.61 28.42,7.5 28.42,6.45 28.28,6.3 J1.33
  03SIG1 w0.102: v1(27.89,7.41) 28.09,7.61 28.2,7.61 28.66,8.08 28.66,9.15 26.97,10.84 26.97,15.07 28.08,16.18 28.08,32.59 29.4,33.91 29.4,35.41 28.08,36.73 28.08,39.13 31.47,42.51 31.88,42.51 32.16,42.8 32.16,44.45 v1(31.63,44.98)
LS_RDATA_A: length 34.7
  TOP w0.152: J1.36 29.78,3.94 v1(29.43,3.59)
  03SIG1 w0.14: v1(29.43,3.59) 30,4.16 30,5.07 32.92,8 34.07,8 35.01,8.94 35.01,29.7 v1(36.93,31.62)
  BOTTOM w0.152: v1(36.93,31.62) R506.1
LS_RDATA_A_S: length 17.9
  03SIG1 w0.14: v1(46.63,46.98) 46.05,46.4 46.05,42.81 44.91,41.68 44.43,41.68 v1(36.93,34.18)
  BOTTOM w0.152: R506.2 v1(36.93,34.18)
LS_RDATA_B: length 35.3
  TOP w0.152: J1.37 30.28,4.82 30.2,4.74 30.2,3.88 v1(30.48,3.6)
  03SIG1 w0.14: v1(38.19,31.66) 37.14,30.6 37.14,9.45 36.13,8.44 35.61,8.44 34.48,7.31 33.28,7.31 31.84,5.86 31.84,4.69 30.74,3.6 v1(30.48,3.6)
  BOTTOM w0.152: v1(38.19,31.66) R505.1
LS_RDATA_B_S: length 18.8
  03SIG1 w0.14: v1(38.19,34.22) 44.85,40.89 45.4,40.89 47.14,42.63 47.14,47.47 v1(46.63,47.98)
  BOTTOM w0.152: R505.2 v1(38.19,34.22)
LS_WDATA_N: length 49.1
  TOP w0.104: v1(28.05,3.57) 27.74,3.26 27.31,3.26 27.03,3.53 27.03,4.63 27.28,4.88 J1.31
  03SIG1 w0.102: v1(32.63,44.98) 33.12,44.5 33.12,42.81 33.53,42.4 33.53,41.33 34.55,40.31 34.55,37.72 29.3,32.47 29.3,8.2 28.46,7.36 28.46,5.72 28.63,5.56 28.63,3.42 28.48,3.27 28.35,3.27 v1(28.05,3.57)
LS_WDATA_P: length 49.8
  TOP w0.104: v1(28.05,2.7) 27.75,3 27.2,3 26.78,3.43 J1.30
  03SIG1 w0.102: v1(33.63,44.98) 34.1,44.51 34.1,42.64 33.78,42.32 33.78,41.44 34.8,40.41 34.8,37.61 29.55,32.36 29.55,8.1 28.71,7.26 28.71,5.83 28.88,5.66 28.88,3.31 28.57,3 28.36,3 v1(28.05,2.7)
MSTR_SCL: length 81.4
  TOP w0.152: J1.50 v1(36.78,7.26)
  04SIG2 w0.14: v1(36.78,7.26) 35.49,5.97 35.49,3.99 32.87,1.37 14.13,1.37 10.6,4.9 10.6,21.39 12.6,23.4 12.6,35.21 v1(13.68,36.29)
  BOTTOM w0.152: U501.8 9.11,40.64 8.78,40.3 8.78,38.23 9.29,37.71 12.26,37.71 v1(13.68,36.29) 14.37,35.6 U500.6 18.23,35.6 18.5,35.87 R503.2
MSTR_SDA: length 86.5
  TOP w0.152: J1.51 37.28,6.66 37.42,6.81 37.42,7.88 v1(36.93,8.38)
  04SIG2 w0.14: v1(36.93,8.38) 37.58,7.73 37.58,6.17 37.11,5.7 37.11,3.92 34.09,0.9 13.61,0.9 10.03,4.48 10.03,21.63 11.65,23.25 11.65,36.87 v1(12.95,38.17)
  BOTTOM w0.152: R501.2 18.52,36.61 18.25,36.87 U500.5 14.25,36.87 v1(12.95,38.17) 12.86,38.08 9.62,38.08 9.19,38.51 9.19,39.75 9.42,39.99 U501.7
P1P8V: length 13.6
  TOP w0.305: J1.2 v1(12.78,4.48) ; J1.1 v1(12.28,6.7) ; J1.80 v1(51.78,4.48) ; J1.79 v1(51.28,6.7)
  BOTTOM w0.508: C502.1 v1(54.03,53.06) ; C503.1 v1(54.03,38.27) ; C518.1 54.38,50.08 54.19,50.27 v1(54.05,50.27) ; C517.1 v1(27.37,50.08) ; C507.1 v1(26.47,38.27) ; C500.1 v1(26.47,53.06) ; C501.1 v1(26.47,40.56) ; C515.1 v1(54.06,43.78) ; C516.1 v1(54.03,40.56) ; v1(23.29,46.24) C510.1
  vias: v1(30.63,50.98) v1(30.63,48.98) v1(30.63,46.98) v1(31.63,47.98) v1(31.63,45.98) v1(32.63,49.98) v1(32.63,48.98) v1(32.63,47.98) v1(32.63,46.98) v1(32.63,42.98) v1(33.63,50.98) v1(46.63,50.98) v1(46.63,45.98) v1(47.63,49.98) v1(47.63,48.98) v1(47.63,47.98) v1(47.63,46.98) v1(47.63,44.98) v1(47.63,42.98) v1(48.63,48.98) v1(48.63,45.98) v1(49.63,49.98) v1(49.63,46.98)
P3P3V: length 2.4
  TOP w0.305: J1.38 30.78,6.25 30.48,6.55 v1(30.48,6.83)
  TOP w0.508: v1(30.48,6.83) 30.48,7 v1(29.87,7.61)
P3P3V_TMP: length 1
  BOTTOM w0.508: R509.2 C520.1
TEMP1N: length 19.5
  BOTTOM w0.152: R508.1 20.75,41.25 20.75,42.23 22.64,44.11 26.31,44.11 28.57,46.38 28.57,46.89 29.17,47.49 33.14,47.49 v1(33.63,47.98)
TEMP1N_S: length 3.1
  BOTTOM w0.152: R508.2 16.47,39.18 C519.2 16.24,39.34 U501.3
TEMP1P: length 19.4
  BOTTOM w0.152: v1(33.63,48.98) 33.14,48.49 29.44,48.49 28.11,47.16 28.11,46.48 26.14,44.52 22.3,44.52 20.18,42.4 20.18,41.66 R507.1
TEMP1P_S: length 3.1
  BOTTOM w0.152: U501.2 16.24,39.99 C519.1 16.46,40.16 R507.2
V_BIAS: length 1
  TOP w0.305: J1.39 31.28,6.57
  vias: v1(31.63,42.98) v1(48.63,42.98)
V_OFFSET: length 5.9
  TOP w0.305: J1.5 v1(14.28,3.96) ; J1.76 v1(49.78,4.48) ; J1.43 33.28,6.62
  BOTTOM w0.508: C506.1 v1(26.38,51.49) ; C511.1 v1(54.04,51.49)
  vias: v1(30.63,43.98) v1(31.63,50.98) v1(31.63,43.98) v1(48.63,50.98) v1(48.63,43.98) v1(49.63,43.98)
V_RESET: length 0.9
  TOP w0.305: 32.72,6.5 32.78,6.44 J1.42
  vias: v1(33.63,43.98) v1(46.63,43.98)

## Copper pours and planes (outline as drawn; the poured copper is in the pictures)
GND on 02GND: 0.54,75.49 81.49,75.49 81.49,0.5 0.54,0.5
GND on 04SIG2: 0.54,75.49 81.49,75.49 81.49,0.5 0.54,0.5 ; 5 cut-outs
P1P8V on 05PWR: 0.54,75.49 81.49,75.49 81.49,0.51 0.54,0.51
P3P3V on BOTTOM: 13.75,16.16 13.75,7.11 14.96,5.9 29.96,5.9 30.76,6.7 30.76,8.44 23.47,15.73 23.47,37.1 22.38,38.2 19.4,38.2 19.3,38.1 19.3,37.44 19.36,37.38 20.08,37.38 20.49,36.98 20.49,35.58 20.01,35.1 19.41,35.1 19.36,35.04 19.36,34.07 18.69,33.39 14.5,33.39 14.5,32.73 15.24,31.98 15.24,25.39 11.28,21.43 5.6,21.43 2.22,24.82 2.22,34.61 2.2,34.62 2.2,49.31 5.52,52.62 10.2,52.62 13.1,49.72 13.1,43.33 13.18,43.25 13.86,43.25 13.86,44.62 15.27,46.03 15.27,52.56 13.35,54.48 4.47,54.48 0.58,50.59 0.58,24.02 6.9,17.7 12.22,17.7
P3P3V_TMP on BOTTOM: 14.42,42.97 14.93,42.97 14.93,42.03 15.44,41.52 15.44,40.43 13.91,40.43 13.91,41.5 14.42,42.01
V_BIAS on TOP: 31.61,6.34 31.14,6.34 30.93,6.65 30.93,7.2 30.53,7.62 29.26,8.89 29.26,31.41 30.29,32.44 31.94,32.44 32.43,31.95 32.43,28.19 31.61,27.36
V_BIAS on BOTTOM: 31.65,27.93 48.8,27.93 55.53,34.67 55.53,37.33 55.4,37.46 53.79,37.46 53.41,37.84 53.41,40.67 54.08,41.33 55.62,41.33 55.9,41.61 55.9,43.01 55.76,43.15 53.13,43.15 52.33,42.35 49.53,42.35 49.25,42.63 49.25,42.97 48.97,43.25 48.43,43.25 48.07,42.88 48.07,41.75 48.39,41.43 49.71,41.43 51.3,39.84 51.3,37.45 45.93,32.08 41.74,32.05 40.91,31.25 35.83,31.25 35.77,31.19 34.83,30.26 33.68,30.26 31.47,32.47 31.47,35.46 29.08,37.85 29.08,40.02 30.37,41.31 30.38,41.31 30.56,41.48 31.93,41.48 32.34,41.89 32.34,43.2 32.05,43.48 31.28,43.48 31.02,43.22 31.02,42.75 30.72,42.45 27.71,42.45 27.02,43.14 25.03,43.14 24.71,42.82 24.7,42.82 24.7,41.65 25.1,41.25 26.58,41.25 27.36,40.46 27.36,33.16 27.82,32.01
V_OFFSET on TOP: 33.46,6.3 33.23,6.3 33.1,6.43 33.1,7.6 34.84,9.34 34.84,12.87 36.09,14.11 36.09,29.34 36.92,30.17 39.11,30.17 39.72,29.56 39.72,13.33 37.17,10.77 37.17,9.83 34.43,7.09 34.1,7.09 33.87,6.85 33.87,6.71
V_OFFSET on BOTTOM: 57.67,24.11 62.37,28.81 62.37,51.04 58.16,55.26 52.62,55.26 50.95,53.59 48.16,53.59 46.13,55.62 34.32,55.62 32.29,53.59 30.13,53.59 28.48,55.24 25.43,55.24 25.3,55.11 25.3,53.84 25.55,53.59 26.57,53.59 26.91,53.25 26.91,52.49 26.74,52.32 25.12,52.32 24.76,51.95 24.76,51.02 25,50.78 27.56,50.78 27.93,50.41 34.03,50.41 34.41,50.79 34.41,51.76 35.41,52.76 44.95,52.76 45.82,51.89 45.82,50.93 46.29,50.46 47.74,50.45 47.98,50.14 48.02,43.82 48.22,43.61 50.02,43.6 50.23,43.41 52.03,43.41 52.33,43.72 52.34,48.86 52.34,49.38 53.82,50.86 55.5,50.86 55.63,50.99 55.63,51.94 55.5,52.07 54.03,52.07 53.56,52.55 53.56,53.18 53.94,53.56 56.89,53.56 58.51,51.93 58.51,36.38 49.69,27.56 37.1,27.55 35.36,25.8 35.36,10.35 30.32,5.31 14.27,5.31 14.03,5.07 14.03,2.35 14.53,1.85 50.07,1.85 57.67,9.45
V_OFFSET on 04SIG2: 31.19,51.45 32.12,51.45 33.13,50.45 33.13,44.53 32.13,43.53 30.4,43.53 30.04,43.9 30.04,50.31
V_RESET on TOP: 32.88,6.33 32.09,6.33 32.09,26.89 32.97,27.77 32.97,32.39 33.6,33.02 35.04,33.02 35.37,32.7 35.37,14.27 34.36,13.26 34.36,9.64 32.88,8.15
V_RESET on BOTTOM: 36.77,35.05 38.28,35.05 38.78,34.55 38.78,33.13 38.89,33.01 41.56,33.01 41.74,33.2 41.74,33.98 41.44,34.28 41.44,34.29 41.16,34.57 41.16,39.16 41.78,39.79 42.12,39.79 45.8,39.78 47.21,41.16 47.2,44.45 47.04,44.75 45.95,44.73 45.85,44.63 45.85,42.99 45.01,42.15 35.35,42.15 34.42,43.09 34.42,44.35 34.19,44.58 33.1,44.58 33.05,44.53 33.05,41.37 34.13,40.29 34.13,36.58 34.13,36.58 34.13,36.22 33.39,35.48 33.39,34.2 33.32,34.13 33.32,33.27 33.03,32.97 33.03,31.54 33.75,30.82 34.82,30.82 35.52,31.52 35.52,33.8

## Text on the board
BOTTOM: 06_BOTTOM
Ref Des/Assembly Bottom: ASSEMBLY_BOTTOM
Ref Des/Silkscreen Bottom: SILKSCREEN_BOTTOM | 9409-D
User.Comments: ASSEMBLY
TOP: 01_TOP
Board Geometry/Soldermask Top: SOLDERMASK_TOP
Ref Des/Silkscreen Top: J | C | B | A | K | D | G | E | F | H | 1 | 2 | 3 | 4 | 5 | 6 | 19 | 20 | 21 | 22 | 23 | 24 | DLP462x DMD EVM | FOR EVALUATION ONLY,NOT FCC | APPROVED FOR RESALE | SILKSCREEN_TOP | Texas Instruments
02GND: 02_GND
03SIG1: 03_SIG1
04SIG2: 04_SIG2
05PWR: 05_PWR
DIMENSION: PASTEMASK_TOP | CUTOUT | SEE DETAIL-A
DISPLAY_TOP: PASTEMASK_BOTTOM
User.18: 76.00 | 68.69 | 65.58 | 55.98 | 52.36 | 51.98 | 47.48 | 47.00 | 42.98 | 42.61 | 38.98 | 30.68 | 27.00 | 4.90 | 0 | 7.78 | 10.00 | 6X | dia | 5.00 | THRU | 25.91 | 28.23 | 31.61 | 35.21 | 4X | 3.40 THRU ALL | 45.01 | 48.61 | 54.31 | 54.70 | 2X | 2.40 | 74.41 | 82.00 | 9.75 | 0.75 | R0.75 | 23.75 | 0.25
User.20: LAYER STACKUP | LAYER 1 - PRIMARY SIDE | LAYER 2 - GND PLANE | LAYER 3 - SIGNAL | LAYER 4 - SIGNAL | LAYER 5 - POWER PLANE | LAYER 6 - SECONDARY SIDE | MINIMUM FINAL | COPPER WEIGHT | 1/2 OZ | 1 OZ | 4.10 WIDTH / 5.90 GAP | 4.00 WIDTH / 6.00 GAP | DIFFERENTIAL IMPEDANCE | 100 OHM (+/- 10%) | SINGLE-ENDED IMPEDANCE | 50 OHM (+/- 10%) | 6.00 WIDTH | 5.50 WIDTH | 10. REFER DETAIL-A FOR CUTOUT. | 11. ALL HOLES IN DRILL CHART ARE FINISHED HOLE SIZES (FHS) | 9. ALL 12.01 MIL  DRILL NEED TO BE NON-CONDUCTIVE VIA FILLING, | 5. REMOVE UNUSED PADS IN ALL INNER LAYERS | 6. DEBURR ALL SHARP EDGES | 7. CLIP SILKSCREEN ON NO MASK AREA | PLATED OVER ON TOP SIDE | FLAT AND SMOOTH ON TOP SIDE | CUTOUT DETAIL-A | 9MM | 9.8MM | R 0.75MM
User.21: DVH2-RP 0.46 DMD | 9409-D | TEXAS INSTRUMENTS | 29 AUG 2022
User.25: LAYER 1 - PRIMARY SIDE
User.26: LAYER 2 - GROUND PLANE
User.27: LAYER 3 - SIGNAL
User.28: LAYER 4 - SIGNAL
User.29: LAYER 5 - POWER PLANE
User.30: LAYER 6 - SECONDARY SIDE
User.39: FIGURE | FINISHED_SIZE | 12.0 | 12.01 | 35.8268 | 94.4882 | 133.8583 | 196.8504 | DRILL CHART: TOP to BOTTOM | ALL UNITS ARE IN MILS | TOLERANCE_DRILL | +3.0/-3.0 | +2.9921/-2.9921 | +2.0/-2.0 | +2.0079/-2.0079 | PLATED | NON-PLATED | QTY | 125 | 112 | 3 | 2 | 4
User.42: Date: November 2023 | PROJECT NUMBER: DLP090_DLP091_DLP092 | FILM LAYER: | REV: A | Texas Instruments
